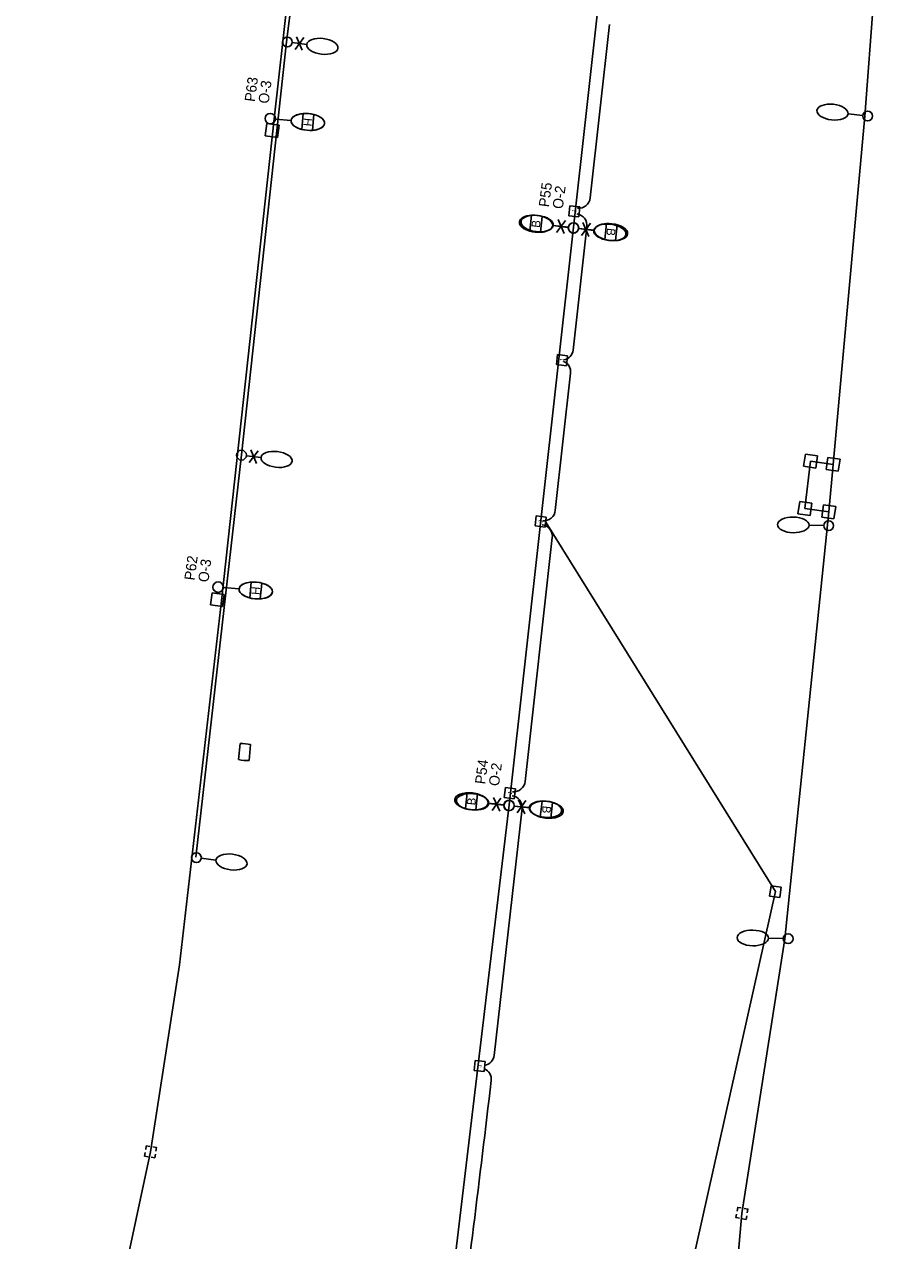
# Model space of a CAD drawing. Extents: x 925407 to 930994, y 604905 to 637063.
# Drawn here: x 930437 to 930857, y 619150 to 619736 of the extents above; entities that cross this region are included whole.
import ezdxf

# ---------------------------------------------------------------- set-up
doc = ezdxf.new("R2010")
doc.units = 0
for name, color, linetype in [('ActivePointCell_dp', 7, 'Continuous'), ('Conduit', 7, 'Continuous'), ('ConduitDB', 7, 'Continuous'), ('ConduitOT', 7, 'Continuous'), ('LiteCond_ep', 7, 'Continuous'), ('Miscellaneous2', 7, 'Continuous'), ('Miscellaneous9', 7, 'Continuous'), ('PoleLight', 7, 'Continuous'), ('PoleLight_ep', 7, 'Continuous'), ('PullBox', 7, 'Continuous')]:
    doc.layers.add(name, color=color, linetype=linetype)

msp = doc.modelspace()

# ---------------------------------------------------------------- linework, layer by layer
at = {"layer": 'Conduit'}
for p, q in [((930826.99, 619524.21), (930842.28, 619692.16)), ((930803.73, 619295.53), (930824.9, 619501.34)), ((930783, 619163.1), (930803.73, 619295.53))]:
    msp.add_line(p, q, dxfattribs=at)
for points in [[(930498.03, 619192.77), (930511.95, 619282.99), (930532.2, 619458.49)], [(930783, 619163.1), (930761.07, 618912.81), (930773.1, 618832.87), (930806.63, 618789.06)]]:
    msp.add_lwpolyline(points, dxfattribs=at)
at = {"layer": 'ConduitDB'}
for q in [(930688.51, 619496.4), (930708.09, 618911.14)]:
    msp.add_line((930799.2, 619318.24), q, dxfattribs=at)
at = {"layer": 'ConduitOT'}
for p, q in [((930557.72, 619690.75), (930584, 619927.03)), ((930709.91, 619652.69), (930719.23, 619736.36)), ((930532.2, 619458.49), (930557.72, 619690.75)), ((930701.74, 619579.35), (930708.35, 619638.73)), ((930693.12, 619502.02), (930700.49, 619568.17)), ((930816.16, 619525.73), (930813.4, 619502.95)), ((930816.16, 619525.73), (930826.99, 619524.21)), ((930813.4, 619502.95), (930824.9, 619501.34)), ((930678.56, 619371.37), (930691.66, 619488.89)), ((930663.68, 619239.26), (930677.13, 619358.52))]:
    msp.add_line(p, q, dxfattribs=at)
msp.add_lwpolyline([(930437.26, 618944.1), (930462.51, 619026.76), (930498.03, 619192.77)], dxfattribs=at)
for centre, radius, start, end in [((930704.43, 619653.18), 5.5, 264.18489, 354.95207), ((930702.9, 619639.47), 5.5, 352.33293, 83.10011), ((930696.27, 619579.96), 5.5, 279.90496, 353.6425), ((930695.02, 619568.78), 5.5, 353.6425, 67.38004), ((930687.64, 619502.51), 5.5, 264.18489, 354.95207), ((930686.2, 619489.62), 5.5, 352.33293, 83.10011), ((930673.08, 619371.86), 5.5, 264.18489, 354.95207), ((930671.65, 619358.97), 5.5, 352.33293, 83.10011), ((930658.22, 619239.9), 5.5, 279.5826, 353.33601), ((930656.79, 619227.73), 5.5, 353.27493, 66.94684), ((919241.37, 620573.8), 11500, 352.568878, 353.274926)]:
    msp.add_arc(centre, radius, start, end, dxfattribs=at)
at = {"layer": 'LiteCond_ep'}
for p, q in [((930563.66, 619727.88), (930588.37, 619926.52)), ((930701.9, 619638.51), (930732.43, 619912.57)), ((930842.28, 619692.16), (930857.13, 619891.83)), ((930541.94, 619528.73), (930563.66, 619727.88)), ((930670.88, 619360.07), (930701.9, 619638.51)), ((930519.95, 619334.87), (930541.94, 619528.73)), ((930824.9, 619501.34), (930826.99, 619524.21)), ((930636.71, 619073.86), (930670.88, 619360.07))]:
    msp.add_line(p, q, dxfattribs=at)
at = {"layer": 'Miscellaneous2'}
for p, q in [((930571.66, 619693.35), (930570.98, 619685.71)), ((930576.06, 619685.26), (930576.74, 619692.9)), ((930570.98, 619685.71), (930570.98, 619685.71)), ((930576.06, 619685.26), (930576.06, 619685.26)), ((930681.71, 619644.3), (930680.86, 619636.69)), ((930681.71, 619644.3), (930681.71, 619644.3)), ((930685.93, 619636.12), (930686.78, 619643.74)), ((930686.78, 619643.74), (930686.78, 619643.74)), ((930717.84, 619640.28), (930716.99, 619632.66)), ((930717.84, 619640.28), (930717.84, 619640.28)), ((930722.06, 619632.1), (930722.91, 619639.72)), ((930722.91, 619639.72), (930722.91, 619639.72)), ((930546.55, 619467.46), (930545.86, 619459.82)), ((930550.94, 619459.37), (930551.63, 619467)), ((930545.86, 619459.82), (930545.86, 619459.82)), ((930550.94, 619459.37), (930550.94, 619459.37)), ((930541.2, 619389.57), (930540.48, 619381.94)), ((930545.56, 619381.46), (930546.28, 619389.09)), ((930540.48, 619381.94), (930540.48, 619381.94)), ((930545.56, 619381.46), (930545.56, 619381.46)), ((930650.63, 619365.87), (930649.78, 619358.25)), ((930650.63, 619365.87), (930650.63, 619365.87)), ((930654.85, 619357.68), (930655.7, 619365.3)), ((930655.7, 619365.3), (930655.7, 619365.3)), ((930686.76, 619361.81), (930685.9, 619354.19)), ((930686.76, 619361.81), (930686.76, 619361.81)), ((930690.97, 619353.62), (930691.83, 619361.24)), ((930691.83, 619361.24), (930691.83, 619361.24))]:
    msp.add_line(p, q, dxfattribs=at)
for centre, major_axis, start_param, end_param in [((930573.86, 619689.3), (-8.05, 0.72), 4.391271, 5.033538), ((930573.86, 619689.3), (-8.05, 0.72), 4.391241, 4.391271), ((930573.86, 619689.3), (-8.05, 0.72), 1.249648, 1.891946), ((930683.82, 619640.21), (8.03, -0.89), 1.249648, 1.891946), ((930719.95, 619636.19), (8.03, -0.89), 1.249648, 1.891946), ((930683.82, 619640.21), (8.03, -0.89), 4.391241, 4.391271), ((930683.82, 619640.21), (8.03, -0.89), 4.391271, 5.033538), ((930719.95, 619636.19), (8.03, -0.89), 4.391241, 4.391271), ((930719.95, 619636.19), (8.03, -0.89), 4.391271, 5.033538), ((930548.75, 619463.41), (-8.05, 0.72), 4.391271, 5.033538), ((930548.75, 619463.41), (-8.05, 0.72), 4.391241, 4.391271), ((930548.75, 619463.41), (-8.05, 0.72), 1.249648, 1.891946), ((930543.38, 619385.51), (-8.04, 0.76), 4.391271, 5.033538), ((930543.38, 619385.51), (-8.04, 0.76), 4.391241, 4.391271), ((930543.38, 619385.51), (-8.04, 0.76), 1.249648, 1.891946), ((930652.74, 619361.77), (8.03, -0.9), 1.249648, 1.891946), ((930688.87, 619357.71), (8.03, -0.9), 1.249648, 1.891946), ((930652.74, 619361.77), (8.03, -0.9), 4.391241, 4.391271), ((930652.74, 619361.77), (8.03, -0.9), 4.391271, 5.033538), ((930688.87, 619357.71), (8.03, -0.9), 4.391241, 4.391271), ((930688.87, 619357.71), (8.03, -0.9), 4.391271, 5.033538)]:
    msp.add_ellipse(centre, major_axis=major_axis, ratio=0.5, start_param=start_param, end_param=end_param, dxfattribs=at)
at = {"layer": 'PoleLight'}
for p, q in [((930558.27, 619690.7), (930565.82, 619690.02)), ((930570.98, 619685.71), (930571.66, 619693.35)), ((930576.74, 619692.9), (930576.06, 619685.26)), ((930680.86, 619636.69), (930681.71, 619644.3)), ((930686.78, 619643.74), (930685.93, 619636.12)), ((930699.38, 619638.48), (930691.85, 619639.32)), ((930704.4, 619637.92), (930711.92, 619637.08)), ((930716.99, 619632.66), (930717.84, 619640.28)), ((930722.91, 619639.72), (930722.06, 619632.1)), ((930545.86, 619459.82), (930546.55, 619467.46)), ((930551.63, 619467), (930550.94, 619459.37)), ((930533.16, 619464.8), (930540.7, 619464.13)), ((930649.78, 619358.25), (930650.63, 619365.87)), ((930655.7, 619365.3), (930654.85, 619357.68)), ((930685.9, 619354.19), (930686.76, 619361.81)), ((930668.29, 619360.02), (930660.77, 619360.87)), ((930673.31, 619359.46), (930680.84, 619358.61)), ((930691.83, 619361.24), (930690.97, 619353.62))]:
    msp.add_line(p, q, dxfattribs=at)
for centre in [(930555.76, 619690.92), (930555.76, 619690.92), (930701.89, 619638.2), (930701.89, 619638.2), (930530.64, 619465.03), (930530.64, 619465.03), (930670.8, 619359.74), (930670.8, 619359.74)]:
    msp.add_circle(centre, 2.52, dxfattribs=at)
for centre, major_axis in [((930573.86, 619689.3), (-8.05, 0.72)), ((930683.82, 619640.21), (8.03, -0.89)), ((930719.95, 619636.19), (8.03, -0.89)), ((930548.75, 619463.41), (-8.05, 0.72)), ((930652.74, 619361.77), (8.03, -0.9)), ((930688.87, 619357.71), (8.03, -0.9))]:
    msp.add_ellipse(centre, major_axis=major_axis, ratio=0.5, dxfattribs=at)
for centre, major_axis, start_param, end_param in [((930573.86, 619689.3), (-8.05, 0.72), 0, 0.847605), ((930573.86, 619689.3), (-8.05, 0.72), 5.033538, 6.283185), ((930573.86, 619689.3), (-8.05, 0.72), 1.891945, 4.391241), ((930573.86, 619689.3), (-8.05, 0.72), 0.847605, 1.249648), ((930683.82, 619640.21), (8.03, -0.89), 1.891945, 4.391241), ((930683.82, 619640.21), (8.03, -0.89), 0.847605, 1.249648), ((930683.82, 619640.21), (8.03, -0.89), 5.033538, 6.283185), ((930683.82, 619640.21), (8.03, -0.89), 0, 0.847605), ((930719.95, 619636.19), (8.03, -0.89), 1.891945, 4.391241), ((930719.95, 619636.19), (8.03, -0.89), 0.847605, 1.249648), ((930719.95, 619636.19), (8.03, -0.89), 0, 0.847605), ((930719.95, 619636.19), (8.03, -0.89), 5.033538, 6.283185), ((930548.75, 619463.41), (-8.05, 0.72), 5.033538, 6.283185), ((930548.75, 619463.41), (-8.05, 0.72), 1.891945, 4.391241), ((930548.75, 619463.41), (-8.05, 0.72), 0, 0.847605), ((930548.75, 619463.41), (-8.05, 0.72), 0.847605, 1.249648), ((930652.74, 619361.77), (8.03, -0.9), 1.891945, 4.391241), ((930652.74, 619361.77), (8.03, -0.9), 0.847605, 1.249648), ((930652.74, 619361.77), (8.03, -0.9), 0, 0.847605), ((930688.87, 619357.71), (8.03, -0.9), 1.891945, 4.391241), ((930652.74, 619361.77), (8.03, -0.9), 5.033538, 6.283185), ((930688.87, 619357.71), (8.03, -0.9), 5.033538, 6.283185), ((930688.87, 619357.71), (8.03, -0.9), 0.847605, 1.249648), ((930688.87, 619357.71), (8.03, -0.9), 0, 0.847605)]:
    msp.add_ellipse(centre, major_axis=major_axis, ratio=0.5, start_param=start_param, end_param=end_param, dxfattribs=at)
at = {"layer": 'PoleLight_ep'}
for p, q in [((930566.3, 619727.54), (930573.34, 619726.68)), ((930571.95, 619729.95), (930567.69, 619724.28)), ((930571.21, 619723.85), (930568.43, 619730.38)), ((930841.29, 619692.41), (930834.23, 619693.2)), ((930699.45, 619638.5), (930692.16, 619639.38)), ((930693.67, 619635.95), (930698.08, 619641.83)), ((930694.43, 619642.27), (930697.32, 619635.51)), ((930704.32, 619637.91), (930711.62, 619637.02)), ((930710.11, 619640.45), (930705.69, 619634.57)), ((930709.34, 619634.13), (930706.46, 619640.89)), ((930544.26, 619528.38), (930551.3, 619527.52)), ((930549.91, 619530.78), (930545.64, 619525.11)), ((930549.17, 619524.68), (930546.39, 619531.21)), ((930822.47, 619494.73), (930815.38, 619494.88)), ((930662.65, 619357.3), (930666.94, 619363.27)), ((930663.29, 619363.64), (930666.31, 619356.94)), ((930678.99, 619362.13), (930674.7, 619356.17)), ((930678.36, 619355.8), (930675.34, 619362.5)), ((930668.38, 619359.96), (930661.07, 619360.7)), ((930673.26, 619359.47), (930680.57, 619358.74)), ((930522.53, 619334.31), (930529.57, 619333.43)), ((930802.97, 619295.58), (930795.87, 619295.73))]:
    msp.add_line(p, q, dxfattribs=at)
for centre, radius in [((930563.95, 619727.83), 2.37), ((930843.64, 619692.15), 2.37), ((930701.89, 619638.2), 2.45), ((930541.91, 619528.66), 2.37), ((930824.84, 619494.69), 2.37), ((930670.82, 619359.72), 2.45), ((930520.18, 619334.6), 2.37), ((930805.33, 619295.54), 2.37)]:
    msp.add_circle(centre, radius, dxfattribs=at)
for centre, major_axis in [((930580.86, 619725.76), (7.51, -0.92)), ((930826.71, 619694.04), (-7.52, 0.84)), ((930684.38, 619640.33), (-7.78, 0.95)), ((930719.4, 619636.07), (7.78, -0.95)), ((930558.81, 619526.6), (7.51, -0.92)), ((930807.81, 619495.03), (-7.57, 0.15)), ((930653.27, 619361.49), (-7.8, 0.79)), ((930688.37, 619357.95), (7.8, -0.79)), ((930537.09, 619332.5), (7.51, -0.93)), ((930788.3, 619295.88), (-7.57, 0.15))]:
    msp.add_ellipse(centre, major_axis=major_axis, ratio=0.5, dxfattribs=at)
at = {"layer": 'PullBox'}
for p, q in [((930553.34, 619682.68), (930554.18, 619688.54)), ((930554.18, 619688.54), (930560.03, 619687.71)), ((930560.03, 619687.71), (930559.2, 619681.85)), ((930559.2, 619681.85), (930553.34, 619682.68)), ((930699.64, 619644.07), (930700.17, 619648.89)), ((930700.17, 619648.89), (930704.99, 619648.35)), ((930704.45, 619643.54), (930699.64, 619644.07)), ((930704.99, 619648.35), (930704.45, 619643.54)), ((930693.62, 619572.3), (930694.16, 619577.12)), ((930694.16, 619577.12), (930698.97, 619576.58)), ((930698.97, 619576.58), (930698.44, 619571.77)), ((930698.44, 619571.77), (930693.62, 619572.3)), ((930812.78, 619523.3), (930813.61, 619529.15)), ((930813.61, 619529.15), (930819.47, 619528.32)), ((930819.47, 619528.32), (930818.63, 619522.46)), ((930823.64, 619521.7), (930824.47, 619527.56)), ((930824.47, 619527.56), (930830.33, 619526.73)), ((930830.33, 619526.73), (930829.5, 619520.87)), ((930818.63, 619522.46), (930812.78, 619523.3)), ((930829.5, 619520.87), (930823.64, 619521.7)), ((930810.06, 619500.44), (930810.89, 619506.3)), ((930810.89, 619506.3), (930816.75, 619505.46)), ((930816.75, 619505.46), (930815.91, 619499.61)), ((930821.56, 619498.83), (930822.39, 619504.69)), ((930822.39, 619504.69), (930828.25, 619503.86)), ((930828.25, 619503.86), (930827.41, 619498)), ((930683.43, 619494.53), (930683.96, 619499.34)), ((930683.96, 619499.34), (930688.78, 619498.81)), ((930688.78, 619498.81), (930688.24, 619493.99)), ((930815.91, 619499.61), (930810.06, 619500.44)), ((930827.41, 619498), (930821.56, 619498.83)), ((930688.24, 619493.99), (930683.43, 619494.53)), ((930526.89, 619456.49), (930527.72, 619462.34)), ((930527.72, 619462.34), (930533.58, 619461.51)), ((930533.58, 619461.51), (930532.75, 619455.66)), ((930532.75, 619455.66), (930526.89, 619456.49)), ((930668.55, 619363.55), (930669.08, 619368.37)), ((930669.08, 619368.37), (930673.9, 619367.83)), ((930673.9, 619367.83), (930673.36, 619363.01)), ((930673.36, 619363.01), (930668.55, 619363.55)), ((930796.38, 619316.11), (930797.07, 619321.06)), ((930797.07, 619321.06), (930802.02, 619320.37)), ((930802.02, 619320.37), (930801.33, 619315.42)), ((930801.33, 619315.42), (930796.38, 619316.11)), ((930653.98, 619232.01), (930654.52, 619236.83)), ((930654.52, 619236.83), (930659.34, 619236.28)), ((930659.34, 619236.28), (930658.79, 619231.47)), ((930658.79, 619231.47), (930653.98, 619232.01))]:
    msp.add_line(p, q, dxfattribs=at)
for points in [[(930495.49, 619192.43), (930495.21, 619190.72), (930496.86, 619190.44)], [(930497.68, 619195.37), (930496.02, 619195.64), (930495.74, 619193.91)], [(930500.67, 619193.09), (930500.96, 619194.83), (930499.21, 619195.12)], [(930500.14, 619189.9), (930500.42, 619191.61)], [(930498.39, 619190.19), (930500.14, 619189.9)], [(930780.46, 619162.75), (930780.18, 619161.04), (930781.83, 619160.77)], [(930782.65, 619165.7), (930781, 619165.97), (930780.71, 619164.23)], [(930785.64, 619163.42), (930785.93, 619165.15), (930784.18, 619165.44)], [(930785.11, 619160.23), (930785.4, 619161.94)], [(930783.36, 619160.51), (930785.11, 619160.23)]]:
    msp.add_lwpolyline(points, dxfattribs=at)

# ---------------------------------------------------------------- texts
at = {"layer": 'ActivePointCell_dp'}
for s, p in [('P63', (930548.31, 619698.79)), ('O-3', (930554.95, 619697.9)), ('P55', (930690.03, 619648.01)), ('O-2', (930696.67, 619647.12)), ('P62', (930519.27, 619468.06)), ('O-3', (930525.91, 619467.17)), ('P54', (930659.31, 619369.78)), ('O-2', (930665.95, 619368.89))]:
    msp.add_text(s, height=5, rotation=82.38819, dxfattribs=at).set_placement(p)
at = {"layer": 'Miscellaneous9'}
for s, rotation, p in [('H', 264.89814, (930572, 619691.34)), ('B', 83.646, (930685.64, 619638.14)), ('B', 263.646, (930718.13, 619638.27)), ('H', 264.89814, (930546.88, 619465.45)), ('B', 83.58637, (930654.56, 619359.69)), ('B', 263.58637, (930687.05, 619359.79))]:
    msp.add_text(s, height=4.08, rotation=rotation, dxfattribs=at).set_placement(p)
at = {"layer": 'PullBox'}
for rotation, p in [(83.6425, (930703.2, 619645.45)), (83.6425, (930697.19, 619573.68)), (83.6425, (930686.99, 619495.91)), (83.6425, (930672.11, 619364.93)), (83.55892, (930657.55, 619233.39))]:
    msp.add_text('J', height=1.94, rotation=rotation, dxfattribs=at).set_placement(p)

doc.saveas('drawing.dxf')
